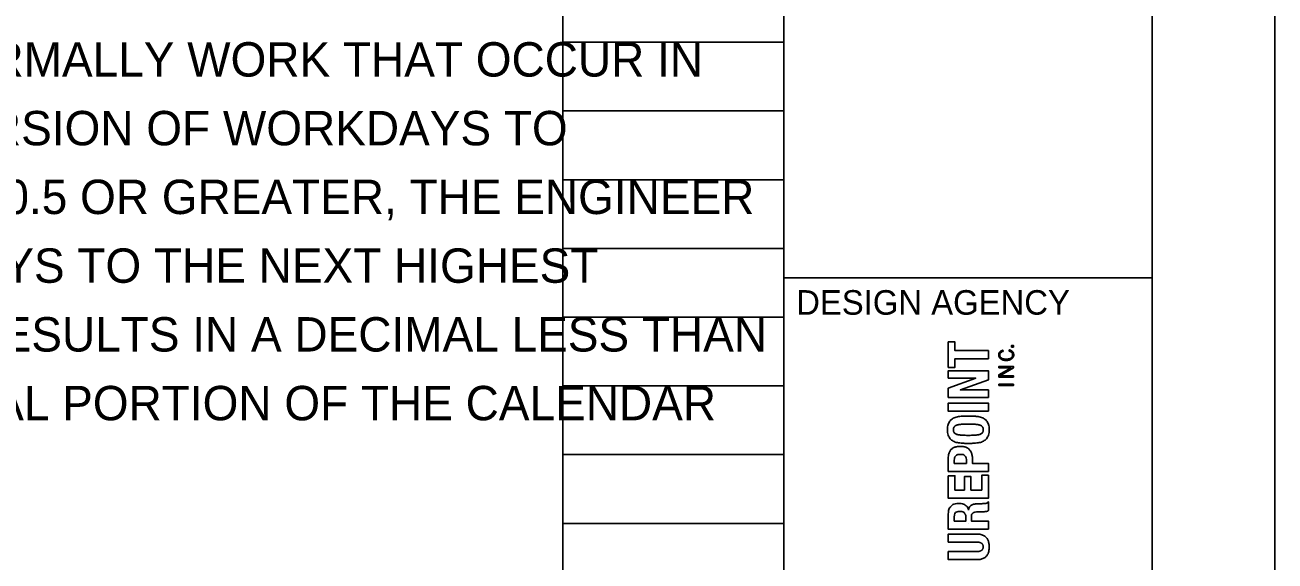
# Model space of a CAD drawing. Extents: x 0 to 84.3, y -13.4 to 22.
# Drawn here: x 28.91 to 34, y 3.35 to 5.53 of the extents above; entities that cross this region are included whole.
import ezdxf

# ---------------------------------------------------------------- set-up
doc = ezdxf.new("R2010")
doc.units = 0
for name, color, linetype in [('SH_Border', 7, 'Continuous'), ('SH_Cut_Line', 7, 'Continuous'), ('SH_Data', 7, 'Continuous'), ('SH_Text', 7, 'Continuous')]:
    doc.layers.add(name, color=color, linetype=linetype)

msp = doc.modelspace()

# ---------------------------------------------------------------- linework, layer by layer
at = {"layer": 'SH_Border'}
for p, q in [((32, 0.5), (32, 21.5)), ((32, 4.5), (33.5, 4.5))]:
    msp.add_line(p, q, dxfattribs=at)
msp.add_lwpolyline([(1.5, 21.5), (33.5, 21.5), (33.5, 0.5), (1.5, 0.5)], close=True, dxfattribs=at)
at = {"layer": 'SH_Cut_Line'}
msp.add_lwpolyline([(0, 0), (34, 0), (34, 22), (0, 22)], close=True, dxfattribs=at)
at = {"layer": 'SH_Data'}
for p, q in [((31.1, 0.98), (31.1, 21.14)), ((32, 0.98), (32, 21.14)), ((31.1, 5.46), (32, 5.46)), ((31.1, 5.18), (32, 5.18)), ((31.1, 4.9), (32, 4.9)), ((31.1, 4.62), (32, 4.62)), ((31.1, 4.34), (32, 4.34)), ((31.1, 4.06), (32, 4.06)), ((31.1, 3.78), (32, 3.78)), ((31.1, 3.5), (32, 3.5)), ((32.75, 3.5), (32.75, 3.5)), ((32.75, 3.5), (32.75, 3.5))]:
    msp.add_line(p, q, dxfattribs=at)
for points in [[(32.6696, 4.2393), (32.6967, 4.2393), (32.6967, 4.2036), (32.8329, 4.2036), (32.8329, 4.1708), (32.6967, 4.1708), (32.6967, 4.1351), (32.6696, 4.1351), (32.6696, 4.2393)], [(32.9349, 4.218), (32.9275, 4.218), (32.9275, 4.225), (32.9349, 4.225), (32.9349, 4.218)], [(32.8754, 4.096), (32.8754, 4.1052), (32.925, 4.1335), (32.925, 4.1337), (32.8754, 4.1337), (32.8754, 4.1391), (32.9349, 4.1391), (32.9349, 4.1335), (32.8798, 4.1016), (32.8798, 4.1014), (32.9349, 4.1014), (32.9349, 4.096), (32.8754, 4.096)], [(32.6696, 4.0513), (32.7815, 4.0912), (32.7815, 4.0916), (32.6696, 4.0916), (32.6696, 4.1218), (32.8329, 4.1218), (32.8329, 4.0842), (32.7185, 4.0439), (32.7185, 4.0435), (32.8329, 4.0435), (32.8329, 4.0134), (32.6696, 4.0134), (32.6696, 4.0513)], [(32.8754, 4.0613), (32.8754, 4.0667), (32.9349, 4.0667), (32.9349, 4.0613), (32.8754, 4.0613)], [(32.8329, 3.957), (32.6696, 3.957), (32.6696, 3.9898), (32.8329, 3.9898), (32.8329, 3.957)], [(32.8329, 3.7115), (32.6696, 3.7115), (32.6696, 3.7691)], [(32.694, 3.7444), (32.7432, 3.7444), (32.7432, 3.759)], [(32.694, 3.7581), (32.694, 3.7444)], [(32.7677, 3.7619), (32.7677, 3.7444), (32.8329, 3.7444), (32.8329, 3.7115)], [(32.6696, 3.6937), (32.6967, 3.6937), (32.6967, 3.6353), (32.7348, 3.6353), (32.7348, 3.6903), (32.7619, 3.6903), (32.7619, 3.6353), (32.8058, 3.6353), (32.8058, 3.696), (32.8329, 3.696), (32.8329, 3.6025), (32.6696, 3.6025), (32.6696, 3.6937)], [(32.8316, 3.5875), (32.8329, 3.5875), (32.8329, 3.5518)], [(32.8329, 3.4763), (32.6696, 3.4763), (32.6696, 3.5373)], [(32.694, 3.5249), (32.694, 3.5092)], [(32.694, 3.5092), (32.7409, 3.5092), (32.7409, 3.5231)], [(32.7519, 3.5538), (32.7524, 3.5538)], [(32.7638, 3.527), (32.7638, 3.5092), (32.8329, 3.5092), (32.8329, 3.4763)], [(32.8158, 3.5477), (32.7844, 3.5468)]]:
    msp.add_lwpolyline(points, dxfattribs=at)
for points in [[(32.8929, 4.2005), (32.8885, 4.1993), (32.8851, 4.1974), (32.8827, 4.195), (32.8803, 4.1926), (32.8791, 4.1896), (32.8791, 4.186), (32.8791, 4.183), (32.8798, 4.1805), (32.8811, 4.1784), (32.8825, 4.1763), (32.8843, 4.1745), (32.8867, 4.1731), (32.889, 4.1717), (32.8918, 4.1707), (32.895, 4.17), (32.8982, 4.1694), (32.9016, 4.169), (32.9052, 4.169), (32.9088, 4.169), (32.9122, 4.1694), (32.9154, 4.17), (32.9186, 4.1707), (32.9214, 4.1717), (32.9237, 4.1732), (32.9261, 4.1746), (32.9279, 4.1764), (32.9293, 4.1786), (32.9306, 4.1809), (32.9313, 4.1835), (32.9313, 4.1866), (32.9313, 4.189), (32.9309, 4.191), (32.9301, 4.1927), (32.9293, 4.1943), (32.9283, 4.1957), (32.9269, 4.1969), (32.9256, 4.1981), (32.9241, 4.199), (32.9223, 4.1997), (32.9206, 4.2005), (32.9187, 4.2011), (32.9168, 4.2016), (32.9168, 4.2016), (32.9177, 4.2067), (32.9177, 4.2067), (32.9203, 4.2062), (32.9228, 4.2054), (32.925, 4.2044), (32.9272, 4.2033), (32.9291, 4.202), (32.9307, 4.2004), (32.9323, 4.1988), (32.9336, 4.1969), (32.9345, 4.1946), (32.9354, 4.1924), (32.9358, 4.1896), (32.9358, 4.1865), (32.9358, 4.1829), (32.9351, 4.1797), (32.9336, 4.1768), (32.9322, 4.174), (32.9301, 4.1716), (32.9274, 4.1697), (32.9247, 4.1677), (32.9215, 4.1662), (32.9177, 4.1652), (32.914, 4.1641), (32.9098, 4.1636), (32.9052, 4.1636), (32.9006, 4.1636), (32.8964, 4.1641), (32.8927, 4.1652), (32.889, 4.1662), (32.8857, 4.1677), (32.883, 4.1697), (32.8803, 4.1716), (32.8783, 4.174), (32.8768, 4.1768), (32.8754, 4.1797), (32.8746, 4.1829), (32.8746, 4.1865), (32.8746, 4.1891), (32.8751, 4.1915), (32.8759, 4.1936), (32.8768, 4.1957), (32.878, 4.1975), (32.8796, 4.1991), (32.8811, 4.2006), (32.8829, 4.202), (32.885, 4.203), (32.8871, 4.204), (32.8894, 4.2049), (32.8918, 4.2056), (32.8918, 4.2056), (32.8929, 4.2005), (32.8929, 4.2005)], [(32.7511, 3.8258), (32.7387, 3.8258), (32.7273, 3.8264), (32.7168, 3.8275), (32.7064, 3.8287), (32.6974, 3.8312), (32.6899, 3.8351), (32.6825, 3.839), (32.6766, 3.8446), (32.6724, 3.8519), (32.6682, 3.8593), (32.6661, 3.8691), (32.6661, 3.8815), (32.6661, 3.8939), (32.6682, 3.9038), (32.6724, 3.9111), (32.6766, 3.9184), (32.6825, 3.9241), (32.6899, 3.928), (32.6974, 3.9319), (32.7064, 3.9344), (32.7168, 3.9355), (32.7273, 3.9367), (32.7387, 3.9373), (32.7511, 3.9373), (32.7578, 3.9373), (32.7643, 3.9371), (32.7705, 3.9367)], [(32.7705, 3.9367), (32.7756, 3.9365), (32.7806, 3.9361), (32.7853, 3.9355), (32.7957, 3.9344), (32.8047, 3.9319), (32.8122, 3.928), (32.8197, 3.9241), (32.8255, 3.9184), (32.8297, 3.9111), (32.8339, 3.9038), (32.836, 3.8939), (32.836, 3.8815), (32.836, 3.8691), (32.8339, 3.8593), (32.8297, 3.8519), (32.8255, 3.8446), (32.8197, 3.839), (32.8122, 3.8351), (32.8047, 3.8312), (32.7957, 3.8287), (32.7853, 3.8275), (32.7748, 3.8264), (32.7634, 3.8258), (32.7511, 3.8258)], [(32.7511, 3.8586), (32.762, 3.8586), (32.7713, 3.8589), (32.779, 3.8594), (32.7867, 3.86), (32.7929, 3.8611), (32.7978, 3.8627), (32.8025, 3.8643), (32.806, 3.8666), (32.8082, 3.8696), (32.8105, 3.8726), (32.8116, 3.8766), (32.8116, 3.8815), (32.8116, 3.8865), (32.8105, 3.8904), (32.8082, 3.8934), (32.806, 3.8964), (32.8025, 3.8988), (32.7978, 3.9004), (32.7929, 3.902), (32.7867, 3.9031), (32.779, 3.9036), (32.7713, 3.9042), (32.762, 3.9044), (32.7511, 3.9044), (32.7401, 3.9044), (32.7308, 3.9042), (32.7232, 3.9036), (32.7156, 3.9031), (32.7094, 3.902), (32.7045, 3.9004), (32.6996, 3.8988), (32.6961, 3.8964), (32.6939, 3.8934), (32.6917, 3.8904), (32.6906, 3.8865), (32.6906, 3.8815), (32.6906, 3.8766), (32.6917, 3.8726), (32.6939, 3.8696), (32.6961, 3.8666), (32.6996, 3.8643), (32.7045, 3.8627), (32.7094, 3.8611), (32.7156, 3.86), (32.7232, 3.8594), (32.7308, 3.8589), (32.7401, 3.8586), (32.7511, 3.8586)], [(32.6696, 3.7691), (32.6696, 3.7774), (32.671, 3.7845), (32.6738, 3.7902), (32.6766, 3.7959), (32.6803, 3.8005), (32.6849, 3.804), (32.6895, 3.8075), (32.6947, 3.81), (32.7005, 3.8115), (32.7064, 3.8131), (32.7124, 3.8138), (32.7185, 3.8138), (32.727, 3.8138), (32.7344, 3.8126), (32.7406, 3.8101), (32.7467, 3.8075), (32.7518, 3.804), (32.7558, 3.7995), (32.7597, 3.795), (32.7627, 3.7896), (32.7647, 3.7832), (32.7667, 3.7768), (32.7677, 3.7697), (32.7677, 3.7619)], [(32.7432, 3.759), (32.7432, 3.7656), (32.7413, 3.7709), (32.7373, 3.7749), (32.7334, 3.779), (32.7273, 3.781), (32.719, 3.781), (32.7109, 3.781), (32.7048, 3.7792), (32.7005, 3.7757), (32.6962, 3.7722), (32.694, 3.7663), (32.694, 3.7581)], [(32.6696, 3.5373), (32.6696, 3.5509), (32.6731, 3.5616), (32.6801, 3.5693), (32.6871, 3.5771), (32.6976, 3.5809), (32.7117, 3.5809), (32.7227, 3.5809), (32.7316, 3.5787), (32.7386, 3.5743), (32.7455, 3.5699), (32.75, 3.5631), (32.7519, 3.5538)], [(32.7524, 3.5538), (32.7532, 3.5594), (32.7546, 3.5639), (32.7566, 3.5673), (32.7587, 3.5707), (32.7617, 3.5733), (32.7655, 3.5752), (32.7694, 3.5771), (32.7744, 3.5784), (32.7803, 3.579), (32.7863, 3.5796), (32.7936, 3.58), (32.8023, 3.5802), (32.811, 3.5803), (32.8176, 3.5808), (32.8222, 3.5816), (32.8268, 3.5825), (32.8299, 3.5844), (32.8316, 3.5875)], [(32.7409, 3.5231), (32.7409, 3.5311), (32.7391, 3.5373), (32.7354, 3.5416), (32.7316, 3.5459), (32.7254, 3.5481), (32.7166, 3.5481), (32.7015, 3.5481), (32.694, 3.5404), (32.694, 3.5249)], [(32.7844, 3.5468), (32.778, 3.5465), (32.773, 3.5448), (32.7693, 3.5418), (32.7657, 3.5388), (32.7638, 3.5338), (32.7638, 3.527)], [(32.8329, 3.5518), (32.8307, 3.5501), (32.828, 3.5491), (32.825, 3.5486), (32.8221, 3.5482), (32.819, 3.5479), (32.8158, 3.5477)], [(32.6696, 3.3852), (32.6696, 3.3852), (32.7832, 3.3852), (32.7832, 3.3852), (32.7874, 3.3852), (32.7911, 3.3854), (32.7946, 3.386), (32.798, 3.3865), (32.8009, 3.3875), (32.8035, 3.389), (32.806, 3.3904), (32.8079, 3.3924), (32.8094, 3.3949), (32.8108, 3.3975), (32.8116, 3.4006), (32.8116, 3.4045), (32.8116, 3.4083), (32.8108, 3.4115), (32.8094, 3.414), (32.8079, 3.4165), (32.806, 3.4185), (32.8035, 3.4199), (32.8009, 3.4214), (32.798, 3.4224), (32.7946, 3.4229), (32.7911, 3.4235), (32.7874, 3.4237), (32.7832, 3.4237), (32.7832, 3.4237), (32.6696, 3.4237), (32.6696, 3.4237), (32.6696, 3.4237), (32.6696, 3.4566), (32.6696, 3.4566), (32.6696, 3.4566), (32.7834, 3.4566), (32.7834, 3.4566), (32.7938, 3.4566), (32.8023, 3.4551), (32.8091, 3.4522), (32.8159, 3.4493), (32.8213, 3.4454), (32.8252, 3.4406), (32.8292, 3.4357), (32.832, 3.4301), (32.8336, 3.4239), (32.8352, 3.4176), (32.836, 3.4112), (32.836, 3.4045), (32.836, 3.3978), (32.8353, 3.3913), (32.8339, 3.385), (32.8326, 3.3788), (32.8299, 3.3732), (32.826, 3.3683), (32.8222, 3.3635), (32.8168, 3.3596), (32.81, 3.3567), (32.8033, 3.3538), (32.7944, 3.3524), (32.7834, 3.3524), (32.7834, 3.3524), (32.6696, 3.3524), (32.6696, 3.3524), (32.6696, 3.3524), (32.6696, 3.3852), (32.6696, 3.3852)]]:
    msp.add_open_spline(points, degree=3, dxfattribs=at)

# ---------------------------------------------------------------- texts
msp.add_text('DESIGN AGENCY', height=0.1, dxfattribs=at).set_placement((32.05, 4.35))
at = {"layer": 'SH_Text'}
for s, p in [('HOLIDAYS THE CONTRACTOR DOES NOT NORMALLY WORK THAT OCCUR IN ', (24.66, 5.32)), ('THE EXTENSION PERIOD. WHEN THE CONVERSION OF WORKDAYS TO ', (24.66, 5.04)), ('CALENDAR DAYS RESULTS IN A DECIMAL OF 0.5 OR GREATER, THE ENGINEER ', (24.66, 4.76)), ('WILL ROUND THE NUMBER OF CALENDAR DAYS TO THE NEXT HIGHEST ', (24.66, 4.48)), ('WHOLE NUMBER. WHEN THE CONVERSION RESULTS IN A DECIMAL LESS THAN ', (24.66, 4.2)), ('0.5, THE ENGINEER WILL DELETE THE DECIMAL PORTION OF THE CALENDAR ', (24.66, 3.92))]:
    msp.add_text(s, height=0.14, dxfattribs=at).set_placement(p)

doc.saveas('drawing.dxf')
